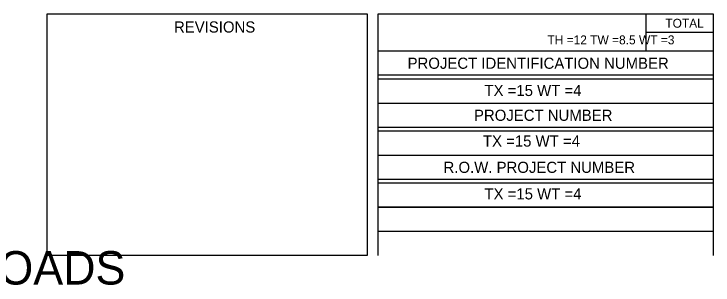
# Model space of a CAD drawing. Extents: x 10196 to 23010, y 6417 to 10189.
# Drawn here: x 12328 to 13268, y 9579 to 9944 of the extents above; entities that cross this region are included whole.
import ezdxf

# ---------------------------------------------------------------- set-up
doc = ezdxf.new("R2010")
doc.units = 0
for name, color, linetype in [('Level 1', 7, 'Continuous'), ('Level 61', 7, 'Continuous'), ('Level 7', 7, 'Continuous')]:
    doc.layers.add(name, color=color, linetype=linetype)

msp = doc.modelspace()

# ---------------------------------------------------------------- linework, layer by layer
at = {"layer": 'Level 1'}
for p, q in [((12817.5, 9684), (12817.5, 9944)), ((12817.5, 9944), (13267.5, 9944)), ((12817.5, 9944), (13267.5, 9944)), ((13177.5, 9894), (13177.5, 9944)), ((13177.5, 9894), (13177.5, 9944)), ((13267.5, 9944), (13267.5, 9684)), ((13267.5, 9944), (13267.5, 9619)), ((13267.5, 9919), (13177.5, 9919)), ((13177.5, 9919), (13177.5, 9919)), ((13267.5, 9919), (13177.5, 9919)), ((13177.5, 9919), (13177.5, 9919)), ((12817.5, 9894), (12817.5, 9894)), ((12817.5, 9894), (12817.5, 9894)), ((12817.5, 9619), (12817.5, 9894)), ((13267.5, 9894), (12817.5, 9894)), ((13267.5, 9861.5), (12817.5, 9861.5)), ((13267.5, 9861.5), (12817.5, 9861.5)), ((13267.5, 9856.5), (12817.5, 9856.5)), ((13267.5, 9856.5), (12817.5, 9856.5)), ((12817.5, 9824), (13267.5, 9824)), ((12817.5, 9824), (13267.5, 9824)), ((13267.5, 9791.5), (12817.5, 9791.5)), ((13267.5, 9791.5), (12817.5, 9791.5)), ((13267.5, 9786.5), (12817.5, 9786.5)), ((13267.5, 9786.5), (12817.5, 9786.5)), ((12817.5, 9754), (13267.5, 9754)), ((12817.5, 9754), (13267.5, 9754)), ((13267.5, 9721.5), (12817.5, 9721.5)), ((13267.5, 9721.5), (12817.5, 9721.5)), ((13267.5, 9716.5), (12817.5, 9716.5)), ((13267.5, 9716.5), (12817.5, 9716.5)), ((13267.5, 9684), (12817.5, 9684)), ((12817.52, 9684), (13267.52, 9684)), ((13267.5, 9651.5), (12817.5, 9651.5))]:
    msp.add_line(p, q, dxfattribs=at)
msp.add_lwpolyline([(12372.5, 9619), (12372.5, 9944), (12802.5, 9944), (12802.5, 9619), (12372.5, 9619)], dxfattribs=at)

# ---------------------------------------------------------------- texts
for s, height, p in [('REVISIONS', 15, (12542.93, 9919)), ('TOTAL', 12, (13203.41, 9925.5)), ('PROJECT IDENTIFICATION NUMBER', 15, (12856.94, 9870.25)), ('PROJECT NUMBER', 15, (12946.19, 9800.25)), ('R.O.W. PROJECT NUMBER', 15, (12905.27, 9730.25))]:
    msp.add_text(s, height=height, dxfattribs=at).set_placement(p)
at = {"layer": 'Level 61'}
for s, height, p in [('TH =12 TW =8.5 WT =3', 12, (13044.9, 9903.16)), ('TX =15 WT =4', 15, (12960.27, 9833.63)), ('TX =15 WT =4', 15, (12958.21, 9765.61)), ('TX =15 WT =4', 15, (12960.27, 9694.58))]:
    msp.add_text(s, height=height, dxfattribs=at).set_placement(p)
at = {"layer": 'Level 7'}
msp.add_text('STATE PARKS AND INSTITUTIONAL ROADS', height=45, dxfattribs=at).set_placement((11220.34, 9580.08))

doc.saveas('drawing.dxf')
